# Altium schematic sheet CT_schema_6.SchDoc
size 383 x 218 mm
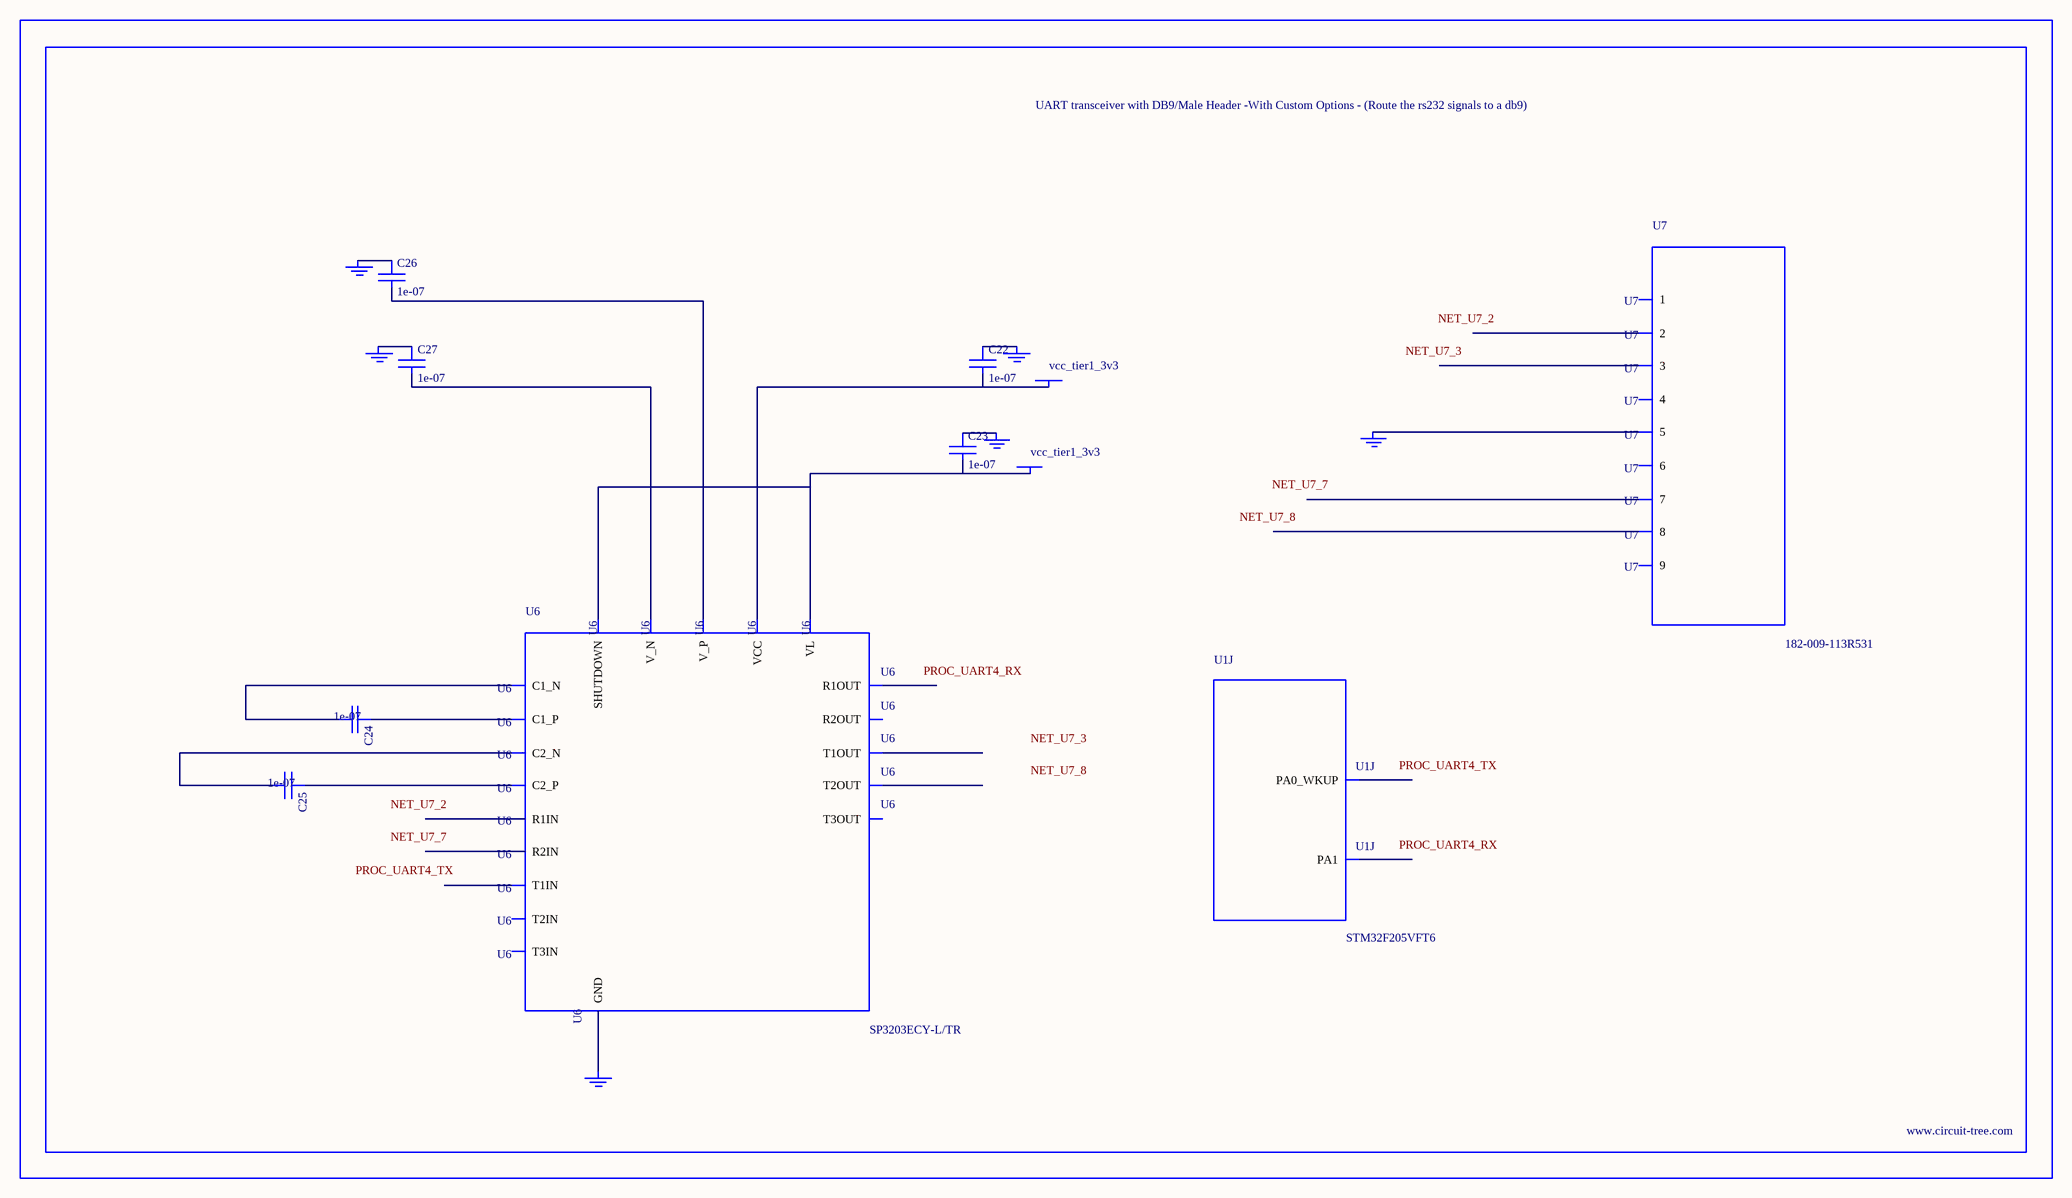
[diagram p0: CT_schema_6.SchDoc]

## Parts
BORDER5  (no value)
C22  1e-07  [C0402]
C23  1e-07  [C0402]
C24  1e-07  [C0402]
C25  1e-07  [C0402]
C26  1e-07  [C0402]
C27  1e-07  [C0402]
GND_INSTANCE_5_0  (no value)
GND_INSTANCE_5_1  (no value)
GND_INSTANCE_5_2  (no value)
GND_INSTANCE_5_3  (no value)
GND_INSTANCE_5_4  (no value)
GND_INSTANCE_5_5  (no value)
POWER_INSTANCE_5_0  vcc_tier1_3v3
POWER_INSTANCE_5_1  vcc_tier1_3v3
U1  STM32F205VFT6  [LQFP100]  (part J of 11)
U6  SP3203ECY-L/TR  [TSSOP20-I]
U7  182-009-113R531  [182-009-MALE]

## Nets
NetC22_1: C22.1 GND_INSTANCE_5_3.0(GND)
NetC22_2: C22.2 POWER_INSTANCE_5_1.0(PWR) U6.19(VCC)
NetC23_1: C23.1 GND_INSTANCE_5_2.0(GND)
NetC23_2: C23.2 POWER_INSTANCE_5_0.0(PWR) U6.12(VL) U6.20(SHUTDOWN)
NetC24_1: C24.1 U6.1(C1_P)
NetC24_2: C24.2 U6.3(C1_N)
NetC25_1: C25.1 U6.4(C2_P)
NetC25_2: C25.2 U6.5(C2_N)
NetC26_1: C26.1 GND_INSTANCE_5_0.0(GND)
NetC26_2: C26.2 U6.2(V_P)
NetC27_1: C27.1 GND_INSTANCE_5_1.0(GND)
NetC27_2: C27.2 U6.6(V_N)
NetGND_INSTANCE_5_4_0: GND_INSTANCE_5_4.0(GND) U6.18(GND)
NetGND_INSTANCE_5_5_0: GND_INSTANCE_5_5.0(GND) U7.5

Not connected (* = marked no-connect by the designer): U1 23(PA0_WKUP) 24(PA1); U6 7(T1IN) 8(T2IN) 9(T3IN) 10(R2OUT) 11(R1OUT) 13(R2IN) 14(R1IN) 15(T3OUT) 16(T2OUT) 17(T1OUT); U7 1 2 3 4 6 7 8 9

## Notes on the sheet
- Labels drawn without touching a wire or pin: NET_U7_2, NET_U7_3, NET_U7_7, NET_U7_8, PROC_UART4_RX, PROC_UART4_TX

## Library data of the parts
BORDER5 = BORDER_PAGE5
C22-C27 = C0402C104K3RACTU
GND_INSTANCE_5_0-GND_INSTANCE_5_5 = GND
POWER_INSTANCE_5_0 POWER_INSTANCE_5_1 = PWR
